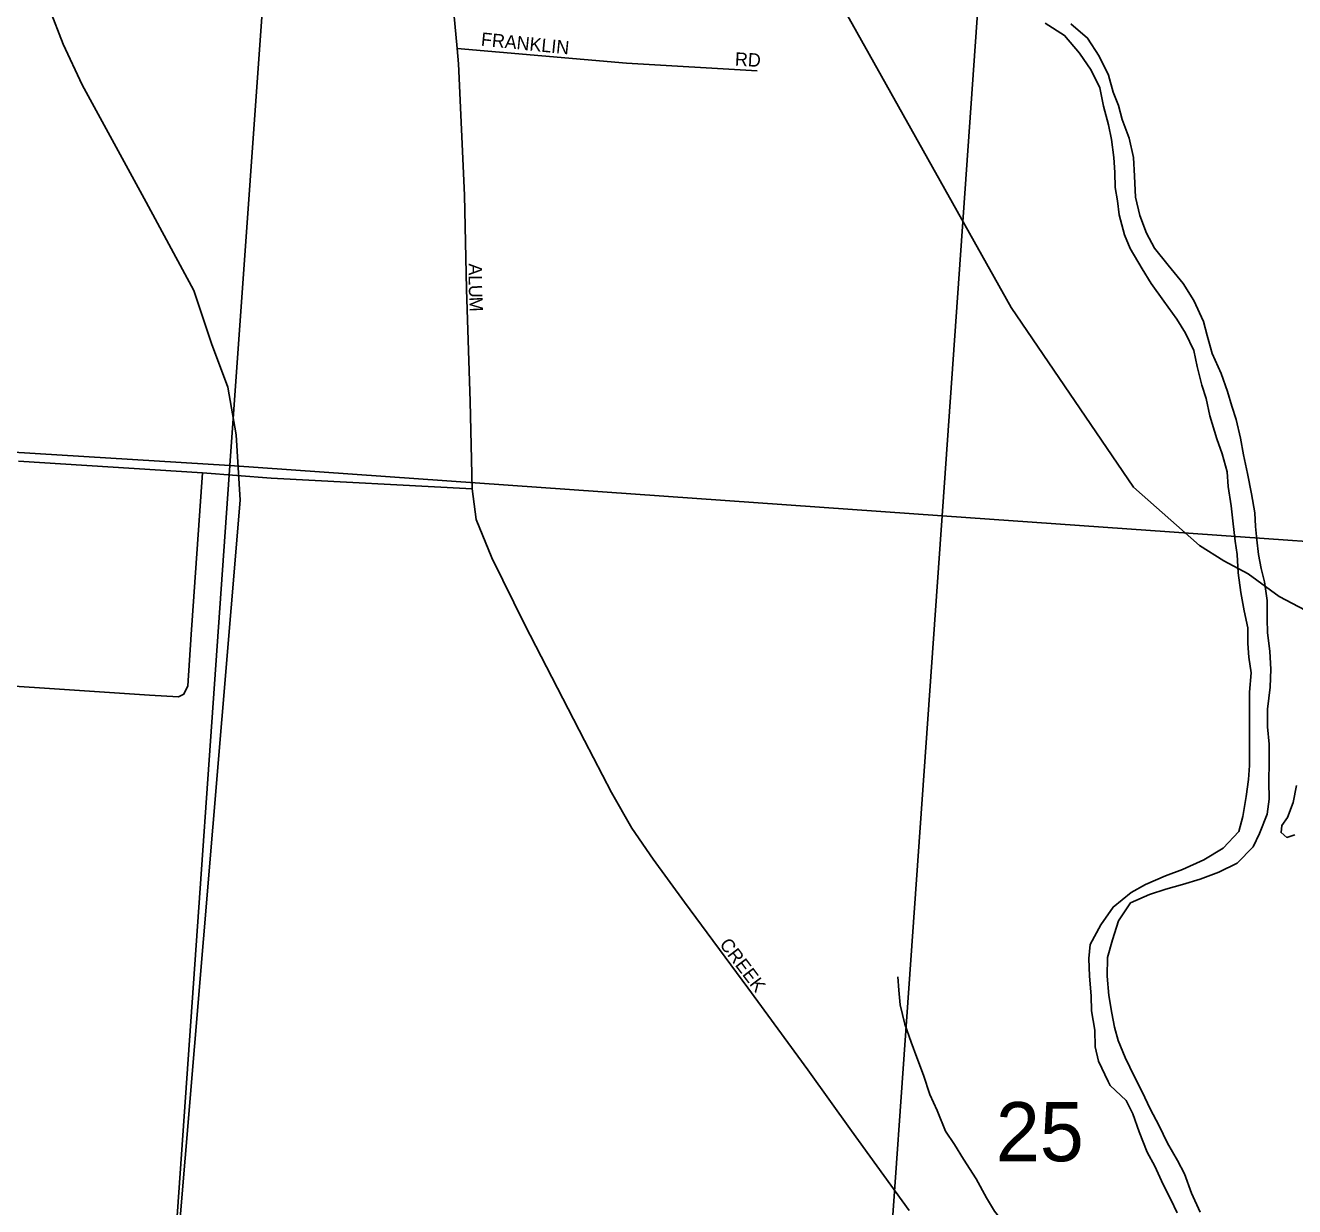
# Model space of a CAD drawing. Extents: x 0 to 34, y 0 to 22.
# Drawn here: x 3.162 to 4.06, y 18.785 to 19.621 of the extents above; entities that cross this region are included whole.
import ezdxf

# ---------------------------------------------------------------- set-up
doc = ezdxf.new("R2010")
doc.units = 0
for name, color, linetype in [('GM_X_City_Street', 7, 'Continuous'), ('GM_X_City_Street_Text', 7, 'Continuous'), ('GM_X_Interstate_Route', 7, 'Continuous'), ('GM_X_Major_River', 7, 'Continuous'), ('GM_X_Minor_Lake', 7, 'Continuous'), ('GM_X_Minor_River', 7, 'Continuous'), ('GM_X_Rail_Line', 7, 'Continuous'), ('GM_X_Section', 7, 'Continuous'), ('GM_X_Section_Text', 7, 'Continuous')]:
    doc.layers.add(name, color=color, linetype=linetype)

msp = doc.modelspace()

# ---------------------------------------------------------------- linework, layer by layer
at = {"layer": 'GM_X_City_Street'}
for points in [[(3.78744, 18.78213), (3.74671, 18.83857), (3.71573, 18.88178), (3.67317, 18.93964), (3.62829, 19.0005), (3.60623, 19.03094), (3.59112, 19.05274), (3.57672, 19.07797), (3.5576, 19.11491), (3.51546, 19.1967), (3.49202, 19.24421), (3.481, 19.27139), (3.47804, 19.293), (3.47677, 19.35488), (3.4741, 19.4346), (3.47277, 19.50105), (3.4684, 19.59403), (3.46739, 19.60501), (3.46436, 19.63765)], [(3.46739, 19.60501), (3.58732, 19.59459), (3.67989, 19.589)], [(3.15685, 19.31276), (3.28711, 19.30448), (3.33579, 19.30059), (3.47804, 19.293)], [(2.6, 19.18876), (2.61039, 19.18816), (2.78893, 19.17672), (2.81264, 19.1752), (2.9509, 19.16674), (3.0827, 19.15804), (3.24972, 19.14703), (3.27018, 19.1458), (3.27401, 19.14761), (3.27679, 19.15363), (3.27912, 19.19003), (3.28711, 19.30448)]]:
    msp.add_lwpolyline(points, dxfattribs=at)
at = {"layer": 'GM_X_Interstate_Route'}
for points in [[(3.40982, 20.31645), (3.41048, 20.29227), (3.41081, 20.25146), (3.41642, 20.21556), (3.4256, 20.17846), (3.43426, 20.15803), (3.43941, 20.146), (3.4467, 20.13029), (3.45848, 20.10561), (3.49544, 20.04006), (3.74165, 19.63209), (3.85961, 19.42144), (3.94621, 19.29429), (3.9931, 19.25309), (4.01013, 19.24202), (4.02755, 19.23284)], [(4.02755, 19.23284), (4.04931, 19.21696), (4.07729, 19.20229), (4.11789, 19.18909)]]:
    msp.add_lwpolyline(points, dxfattribs=at)
at = {"layer": 'GM_X_Major_River'}
for points in [[(3.88383, 19.62288), (3.89746, 19.61416), (3.90806, 19.60164), (3.91638, 19.58951), (3.92244, 19.57699), (3.92509, 19.5641), (3.92849, 19.55082), (3.93076, 19.54058), (3.93227, 19.52768), (3.93303, 19.51706), (3.9334, 19.50644), (3.93491, 19.49696), (3.93605, 19.4871), (3.93983, 19.47306), (3.94399, 19.4632), (3.95232, 19.44879), (3.95876, 19.43855), (3.96784, 19.42604), (3.97692, 19.41315), (3.98298, 19.40329), (3.98904, 19.39115), (3.9913, 19.37977), (3.99471, 19.3665), (3.99773, 19.35702), (4.00038, 19.34488), (4.0053, 19.32857), (4.00909, 19.31795), (4.01249, 19.30505), (4.01325, 19.29481), (4.01552, 19.28116), (4.01665, 19.27053), (4.01816, 19.25612), (4.01967, 19.24664), (4.02042, 19.23374), (4.02231, 19.2197), (4.02458, 19.20681), (4.02723, 19.19467), (4.02723, 19.18367), (4.02798, 19.17381), (4.0295, 19.16281), (4.02836, 19.14915), (4.02834, 19.09718), (4.02759, 19.08732), (4.02607, 19.07518), (4.02379, 19.06114), (4.02076, 19.05052), (4.00978, 19.03876), (3.99614, 19.0304), (3.98099, 19.02357), (3.96888, 19.01901), (3.95487, 19.01293), (3.94464, 19.00724), (3.93177, 18.99699), (3.92305, 18.98447), (3.91548, 18.97043), (3.91472, 18.96057), (3.91509, 18.94805), (3.91622, 18.93401), (3.9166, 18.92339), (3.91887, 18.90974), (3.91925, 18.89798), (3.92152, 18.88774), (3.92833, 18.87333)], [(3.902, 19.62251), (3.91374, 19.61227), (3.92207, 19.59938), (3.9285, 19.5861), (3.9319, 19.57396), (3.93569, 19.56448), (3.93834, 19.55462), (3.94326, 19.54135), (3.94628, 19.52769), (3.94703, 19.51442), (3.94779, 19.49962), (3.95081, 19.48673), (3.95536, 19.47421), (3.96103, 19.46359), (3.97088, 19.45146), (3.98147, 19.43856), (3.98904, 19.42643), (3.99586, 19.41164), (3.9985, 19.40178), (4.00191, 19.38888), (4.00834, 19.37485), (4.01288, 19.36195), (4.01591, 19.35171), (4.01894, 19.34223)], [(4.01894, 19.34223), (4.02196, 19.32895), (4.02423, 19.3172), (4.02688, 19.30392), (4.02991, 19.28951), (4.03217, 19.27623), (4.03255, 19.26637), (4.03368, 19.25689), (4.03482, 19.24664), (4.03671, 19.23678), (4.03898, 19.2273), (4.04087, 19.21402), (4.04086, 19.20075), (4.04124, 19.19127), (4.04275, 19.17799), (4.04351, 19.16547), (4.04313, 19.15257), (4.04123, 19.13702), (4.04122, 19.1245), (4.04236, 19.11236), (4.04235, 19.09947), (4.04197, 19.08581), (4.04235, 19.07329), (4.04083, 19.06267), (4.03553, 19.04901), (4.03098, 19.03953), (4.01962, 19.02814), (4.00674, 19.02168), (3.99349, 19.01675), (3.98099, 19.01295), (3.96925, 19.00953), (3.95752, 19.00573), (3.94426, 19.00003), (3.93555, 18.98713), (3.93138, 18.97385), (3.92797, 18.96133), (3.92759, 18.94805), (3.92872, 18.9344), (3.93099, 18.92188), (3.93288, 18.91202), (3.93553, 18.90254), (3.94045, 18.8904), (3.94688, 18.87675), (3.95218, 18.86651), (3.95824, 18.85362), (3.96429, 18.84262), (3.97035, 18.82973), (3.97754, 18.81759), (3.98246, 18.80811), (3.98738, 18.79446), (3.99343, 18.78081)], [(3.92833, 18.87333), (3.92984, 18.87067), (3.9412, 18.86006), (3.94574, 18.85058), (3.95028, 18.83768), (3.95596, 18.82327), (3.96126, 18.81341), (3.96731, 18.80052), (3.97261, 18.7899), (3.97715, 18.78042)]]:
    msp.add_lwpolyline(points, dxfattribs=at)
at = {"layer": 'GM_X_Minor_Lake'}
msp.add_lwpolyline([(4.06169, 19.08304), (4.0593, 19.07092), (4.05541, 19.06032), (4.05119, 19.05466), (4.05077, 19.04973), (4.0549, 19.04628), (4.0606, 19.04813)], dxfattribs=at)
at = {"layer": 'GM_X_Minor_River'}
msp.add_lwpolyline([(3.77944, 18.94758), (3.78011, 18.93808), (3.78114, 18.92783), (3.78442, 18.91414), (3.78884, 18.90119), (3.7929, 18.89053), (3.79771, 18.87797), (3.80212, 18.86427), (3.80731, 18.85284), (3.81323, 18.83837), (3.81958, 18.82883), (3.82592, 18.81853), (3.83487, 18.80441), (3.84231, 18.79107), (3.8479, 18.78153), (3.85651, 18.77046), (3.86509, 18.75748), (3.87366, 18.74223), (3.88264, 18.73153), (3.89049, 18.72084), (3.89795, 18.70939), (3.90767, 18.69603), (3.91553, 18.6861)], dxfattribs=at)
at = {"layer": 'GM_X_Rail_Line'}
msp.add_lwpolyline([(3.24228, 18.42761), (3.26853, 18.74288), (3.31378, 19.28503), (3.31089, 19.33131), (3.30511, 19.36506), (3.29355, 19.39591), (3.28103, 19.43351), (3.24731, 19.49618), (3.20203, 19.5791), (3.18855, 19.60803), (3.17892, 19.63309), (3.17025, 19.66588), (3.16543, 19.70251), (3.16255, 19.74108), (3.16448, 19.86064), (3.19533, 20.35523), (3.21268, 20.65312), (3.21364, 20.71674), (3.21171, 20.76398), (3.20409, 20.80854), (3.19954, 20.83827)], dxfattribs=at)
at = {"layer": 'GM_X_Section'}
for points in [[(3.37876, 20.32228), (3.30645, 19.30967), (2.80475, 19.34047), (2.87497, 20.35724)], [(3.88174, 20.28496), (3.81078, 19.27405), (3.30645, 19.30967), (3.37876, 20.32228)], [(4.3834, 20.24774), (4.31376, 19.23853), (3.81078, 19.27405), (3.88174, 20.28496)], [(3.30645, 19.30967), (3.23526, 18.29366), (2.73415, 18.3252), (2.80475, 19.34047)], [(3.81078, 19.27405), (3.73924, 18.26012), (3.23526, 18.29366), (3.30645, 19.30967)], [(4.31376, 19.23853), (4.24183, 18.22667), (3.73924, 18.26012), (3.81078, 19.27405)]]:
    msp.add_lwpolyline(points, close=True, dxfattribs=at)

# ---------------------------------------------------------------- texts
at = {"layer": 'GM_X_City_Street_Text'}
for s, rotation, p in [('FRANKLIN', 354.28941, (3.484, 19.60697)), ('RD', 356.97695, (3.66391, 19.59281)), ('A', 270.04373, (3.47561, 19.45273)), ('U', 271.8415, (3.47563, 19.43741)), ('L', 270.0705, (3.47561, 19.44439)), ('M', 272.96192, (3.47591, 19.42888)), ('CREEK', 307.11768, (3.65274, 18.97048))]:
    msp.add_text(s, height=0.00947, rotation=rotation, dxfattribs=at).set_placement(p)
at = {"layer": 'GM_X_Section_Text'}
msp.add_text('25', height=0.041856, rotation=0.00001, dxfattribs=at).set_placement((3.84882, 18.81696))

doc.saveas('drawing.dxf')
